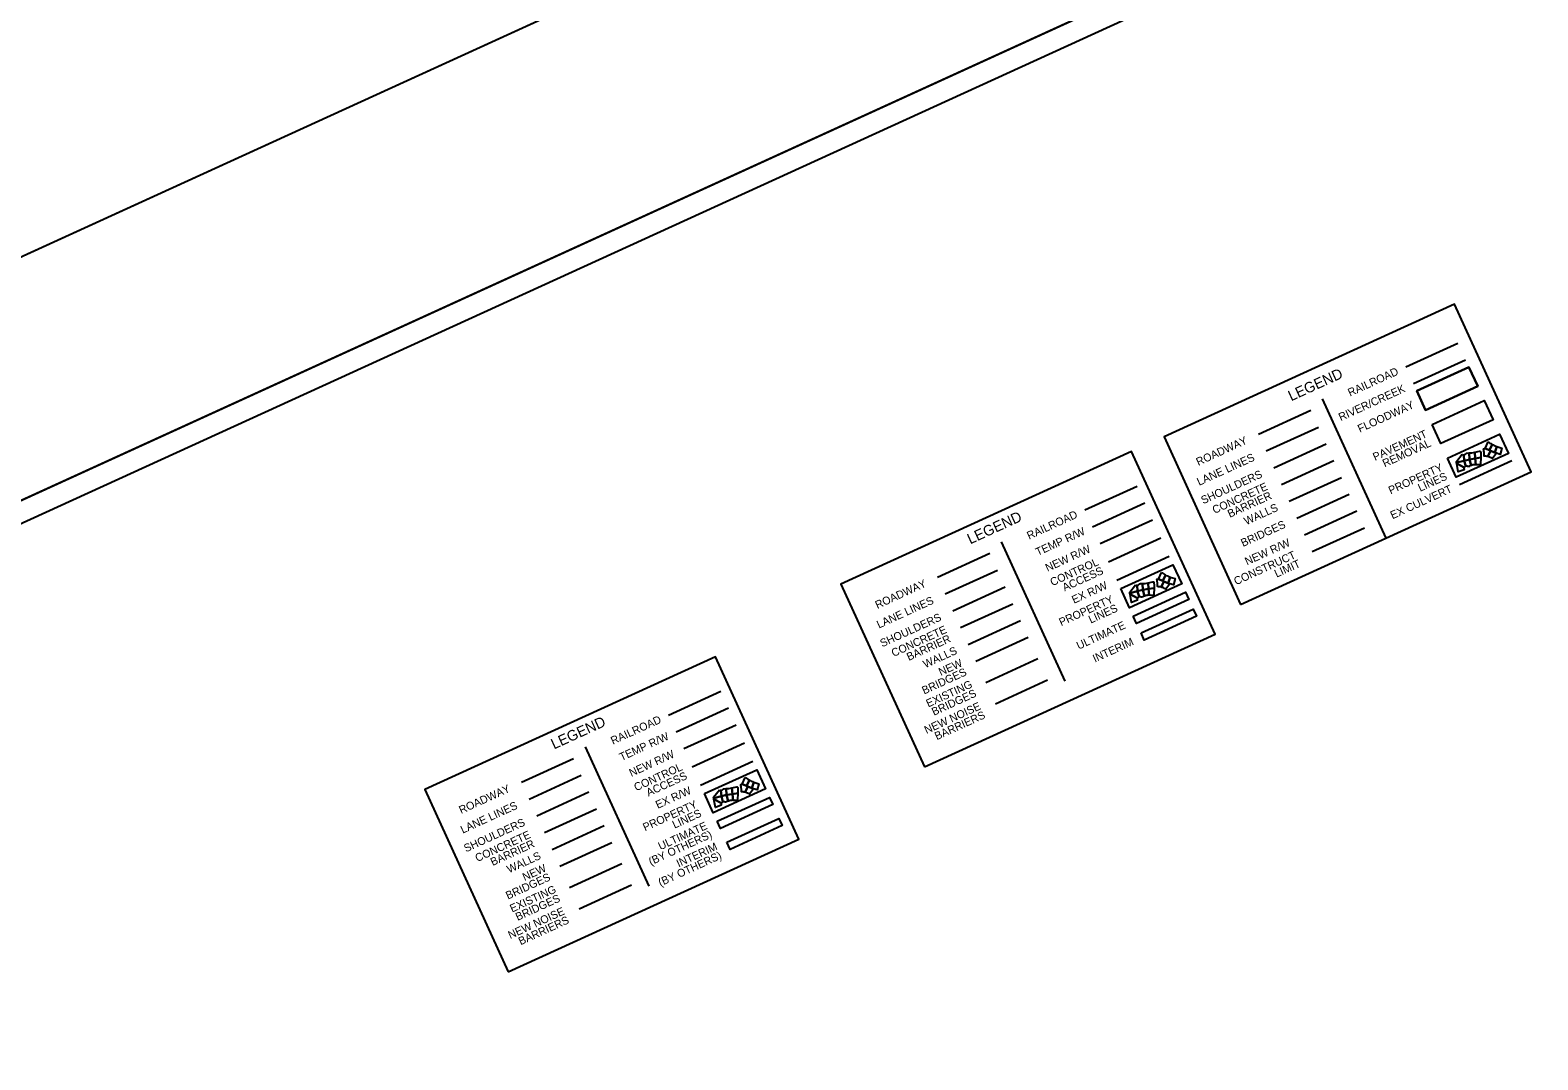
# Model space of a CAD drawing. Extents: x 1952253 to 1982336, y 791177 to 808695.
# Drawn here: x 1960851 to 1967995, y 791177 to 796057 of the extents above; entities that cross this region are included whole.
import ezdxf

# ---------------------------------------------------------------- set-up
doc = ezdxf.new("R2010")
doc.units = 0
for name, color, linetype in [('Default', 7, 'Continuous'), ('RD_SHT_Bndy', 7, 'Continuous'), ('RD_SHT_IplotShp', 7, 'Continuous'), ('RD_SHT_ShtClip', 7, 'Continuous'), ('RD_SHT_TX', 7, 'Continuous'), ('RD_Sketch1', 7, 'Continuous')]:
    doc.layers.add(name, color=color, linetype=linetype)

msp = doc.modelspace()

# ---------------------------------------------------------------- linework, layer by layer
at = {"layer": 'Default'}
for points in [[(1967759.2, 794105.8), (1967762.3, 794103.5), (1967767.2, 794100.2), (1967772.2, 794097.1), (1967777.2, 794094.1), (1967779.2, 794093), (1967765.5, 794065.6), (1967745, 794074.2)], [(1967779.2, 794093), (1967782.4, 794091.3), (1967787.7, 794088.7), (1967793, 794086.3), (1967798.4, 794084.1), (1967800.1, 794083.4), (1967790.8, 794055), (1967771.3, 794063.2), (1967765.5, 794065.6)], [(1967636.5, 794046.8), (1967638.1, 794045.9), (1967639.6, 794045.3), (1967641.1, 794044.9), (1967642.7, 794044.7), (1967644.3, 794044.7), (1967646.2, 794016.4), (1967610, 794007.3), (1967609.1, 794012.1)], [(1967646.2, 794016.4), (1967653.7, 793990), (1967652.2, 793989.5), (1967650.8, 793988.8), (1967649.5, 793987.9), (1967648.3, 793986.8), (1967647.3, 793985.7), (1967646.2, 793984.1), (1967610.9, 794002.4), (1967610, 794007.3)], [(1967652.9, 794049), (1967653.9, 794050), (1967655, 794050.8), (1967656.3, 794051.5), (1967657.6, 794052), (1967660, 794052.4), (1967668.8, 794052.9), (1967671, 794022.6), (1967646.2, 794016.4), (1967644.3, 794044.7), (1967646.2, 794045), (1967647.8, 794045.4), (1967649.2, 794046.1), (1967650.6, 794046.9), (1967651.8, 794047.9)], [(1967671, 794022.6), (1967678.4, 793993.3), (1967677.3, 793992.9), (1967674.1, 793991.4), (1967670.9, 793989.9), (1967670.4, 793989.6), (1967669.1, 793989.1), (1967667.7, 793988.8), (1967666.3, 793988.7), (1967664.9, 793988.7), (1967663.5, 793989), (1967662.2, 793989.5), (1967661.5, 793989.8), (1967660, 793990.2), (1967658.4, 793990.5), (1967656.8, 793990.5), (1967655.3, 793990.4), (1967653.7, 793990), (1967646.2, 794016.4)], [(1967696, 794056.5), (1967698.1, 794027.2), (1967671, 794022.6), (1967668.8, 794052.9), (1967681.8, 794053.5)], [(1967698.1, 794027.2), (1967701.4, 793997.3), (1967699.6, 793997.3), (1967698, 793997.3), (1967694.5, 793997.1), (1967691, 793996.6), (1967687.5, 793996), (1967684.1, 793995.1), (1967680.7, 793994.1), (1967678.4, 793993.3), (1967671, 794022.6)], [(1967724.4, 794031.6), (1967698.1, 794027.2), (1967696, 794056.5), (1967719.1, 794061.3), (1967720.1, 794061.4), (1967721, 794061.3), (1967721.8, 794060.9), (1967722.5, 794060.4), (1967723, 794059.7), (1967723.4, 794059), (1967723.6, 794058.1), (1967724, 794054.5), (1967724.4, 794048.8), (1967724.7, 794043.1), (1967724.7, 794037.4)], [(1967724.4, 794031.6), (1967722.9, 794000.1), (1967722.9, 793999.5), (1967722.6, 793998.7), (1967722.1, 793997.9), (1967721.5, 793997.3), (1967720.7, 793996.9), (1967719.9, 793996.6), (1967719.1, 793996.6), (1967701.4, 793997.3), (1967698.1, 794027.2)], [(1967745, 794074.2), (1967765.5, 794065.6), (1967771.3, 794063.2), (1967758.5, 794035.5), (1967757.4, 794035.8), (1967753.3, 794036.7), (1967749.1, 794037.5), (1967744.9, 794038), (1967741.2, 794038.4), (1967741.1, 794044.4), (1967740.9, 794050.3), (1967740.4, 794056.3), (1967739.7, 794062.3), (1967738.8, 794068.2), (1967738, 794072.8)], [(1967771.3, 794063.2), (1967790.8, 794055), (1967799.1, 794052.1), (1967779.8, 794026.7), (1967777.1, 794028.2), (1967773.4, 794030.1), (1967769.5, 794031.8), (1967765.5, 794033.3), (1967761.5, 794034.6), (1967758.5, 794035.5)], [(1967800.1, 794083.4), (1967803.9, 794082), (1967805.2, 794081.6), (1967824.1, 794076.2), (1967815.6, 794046.3), (1967799.1, 794052.1), (1967790.8, 794055)], [(1967646.2, 793984.1), (1967645.7, 793982.9), (1967645.1, 793981.4), (1967644.8, 793979.9), (1967644.7, 793978.3), (1967644.7, 793976.7), (1967645, 793975.2), (1967645.5, 793973.7), (1967617.8, 793963.3), (1967610.9, 794002.4)], [(1966176.6, 793412.8), (1966150.3, 793408.4), (1966148.1, 793437.7), (1966171.2, 793442.6), (1966172.3, 793442.7), (1966173.1, 793442.5), (1966173.9, 793442.2), (1966174.6, 793441.7), (1966175.1, 793441), (1966175.5, 793440.2), (1966175.7, 793439.4), (1966176.1, 793435.7), (1966176.6, 793430.1), (1966176.8, 793424.4), (1966176.9, 793418.6)], [(1966197.1, 793455.5), (1966217.6, 793446.9), (1966223.4, 793444.4), (1966210.6, 793416.7), (1966209.6, 793417), (1966205.4, 793418), (1966201.3, 793418.7), (1966197.1, 793419.3), (1966193.4, 793419.6), (1966193.3, 793425.6), (1966193, 793431.6), (1966192.5, 793437.6), (1966191.8, 793443.5), (1966191, 793449.4), (1966190.1, 793454.1)], [(1966211.3, 793487), (1966214.5, 793484.7), (1966219.3, 793481.4), (1966224.3, 793478.3), (1966229.4, 793475.4), (1966231.4, 793474.3), (1966217.6, 793446.9), (1966197.1, 793455.5)], [(1966223.4, 793444.4), (1966243, 793436.2), (1966251.3, 793433.3), (1966231.9, 793407.9), (1966229.3, 793409.4), (1966225.5, 793411.3), (1966221.6, 793413), (1966217.7, 793414.6), (1966213.6, 793415.9), (1966210.6, 793416.7)], [(1966231.4, 793474.3), (1966234.5, 793472.6), (1966239.8, 793470), (1966245.1, 793467.6), (1966250.6, 793465.3), (1966252.3, 793464.7), (1966243, 793436.2), (1966223.4, 793444.4), (1966217.6, 793446.9)], [(1966252.3, 793464.7), (1966256.1, 793463.3), (1966257.4, 793462.8), (1966276.2, 793457.4), (1966267.8, 793427.6), (1966251.3, 793433.3), (1966243, 793436.2)], [(1966088.7, 793428.1), (1966090.3, 793427.1), (1966091.7, 793426.6), (1966093.3, 793426.2), (1966094.8, 793426), (1966096.4, 793426), (1966098.3, 793397.6), (1966062.1, 793388.5), (1966061.3, 793393.4)], [(1966098.3, 793397.6), (1966105.8, 793371.3), (1966104.3, 793370.8), (1966102.9, 793370), (1966101.6, 793369.2), (1966100.4, 793368.1), (1966099.4, 793366.9), (1966098.4, 793365.3), (1966063, 793383.6), (1966062.1, 793388.5)], [(1966098.4, 793365.3), (1966097.8, 793364.2), (1966097.3, 793362.7), (1966097, 793361.2), (1966096.8, 793359.6), (1966096.9, 793358), (1966097.2, 793356.4), (1966097.6, 793354.9), (1966069.9, 793344.6), (1966063, 793383.6)], [(1966105.1, 793430.3), (1966106, 793431.3), (1966107.2, 793432.1), (1966108.4, 793432.8), (1966109.7, 793433.3), (1966112.1, 793433.7), (1966120.9, 793434.1), (1966123.2, 793403.9), (1966098.3, 793397.6), (1966096.4, 793426), (1966098.4, 793426.3), (1966099.9, 793426.7), (1966101.3, 793427.3), (1966102.7, 793428.2), (1966103.9, 793429.1)], [(1966123.2, 793403.9), (1966130.6, 793374.5), (1966129.5, 793374.1), (1966126.2, 793372.7), (1966123.1, 793371.1), (1966122.6, 793370.9), (1966121.2, 793370.4), (1966119.9, 793370), (1966118.5, 793369.9), (1966117, 793370), (1966115.7, 793370.3), (1966114.3, 793370.8), (1966113.6, 793371), (1966112.1, 793371.5), (1966110.6, 793371.7), (1966109, 793371.8), (1966107.4, 793371.7), (1966105.8, 793371.3), (1966098.3, 793397.6)], [(1966148.1, 793437.7), (1966150.3, 793408.4), (1966123.2, 793403.9), (1966120.9, 793434.1), (1966133.9, 793434.7)], [(1966150.3, 793408.4), (1966153.6, 793378.5), (1966151.7, 793378.6), (1966150.2, 793378.6), (1966146.6, 793378.3), (1966143.1, 793377.9), (1966139.6, 793377.2), (1966136.2, 793376.4), (1966132.8, 793375.3), (1966130.6, 793374.5), (1966123.2, 793403.9)], [(1966176.6, 793412.8), (1966175.1, 793381.4), (1966175, 793380.7), (1966174.7, 793379.9), (1966174.2, 793379.2), (1966173.6, 793378.6), (1966172.9, 793378.1), (1966172.1, 793377.9), (1966171.2, 793377.8), (1966153.6, 793378.5), (1966150.3, 793408.4)], [(1964239.3, 792515), (1964242.5, 792512.7), (1964247.3, 792509.4), (1964252.3, 792506.3), (1964257.4, 792503.4), (1964259.4, 792502.3), (1964245.6, 792474.9), (1964225.1, 792483.5)], [(1964116.7, 792456.1), (1964118.3, 792455.1), (1964119.8, 792454.6), (1964121.3, 792454.2), (1964122.9, 792454), (1964124.4, 792454), (1964126.3, 792425.6), (1964090.1, 792416.5), (1964089.3, 792421.4)], [(1964133.1, 792458.3), (1964134.1, 792459.3), (1964135.2, 792460.1), (1964136.4, 792460.8), (1964137.7, 792461.3), (1964140.1, 792461.7), (1964148.9, 792462.1), (1964151.2, 792431.9), (1964126.3, 792425.6), (1964124.4, 792454), (1964126.4, 792454.3), (1964127.9, 792454.7), (1964129.3, 792455.3), (1964130.7, 792456.1), (1964131.9, 792457.1)], [(1964176.1, 792465.7), (1964178.3, 792436.4), (1964151.2, 792431.9), (1964148.9, 792462.1), (1964161.9, 792462.7)], [(1964204.6, 792440.8), (1964178.3, 792436.4), (1964176.1, 792465.7), (1964199.2, 792470.6), (1964200.3, 792470.7), (1964201.1, 792470.5), (1964201.9, 792470.2), (1964202.6, 792469.6), (1964203.2, 792469), (1964203.5, 792468.2), (1964203.7, 792467.4), (1964204.1, 792463.7), (1964204.6, 792458), (1964204.8, 792452.3), (1964204.9, 792446.6)], [(1964225.1, 792483.5), (1964245.6, 792474.9), (1964251.4, 792472.4), (1964238.6, 792444.7), (1964237.6, 792445), (1964233.4, 792446), (1964229.3, 792446.7), (1964225.1, 792447.3), (1964221.4, 792447.6), (1964221.3, 792453.6), (1964221, 792459.6), (1964220.5, 792465.6), (1964219.8, 792471.5), (1964219, 792477.4), (1964218.1, 792482)], [(1964251.4, 792472.4), (1964271, 792464.2), (1964279.3, 792461.3), (1964259.9, 792435.9), (1964257.3, 792437.4), (1964253.5, 792439.3), (1964249.6, 792441), (1964245.7, 792442.5), (1964241.6, 792443.9), (1964238.6, 792444.7)], [(1964259.4, 792502.3), (1964262.5, 792500.6), (1964267.8, 792498), (1964273.1, 792495.6), (1964278.6, 792493.3), (1964280.3, 792492.7), (1964271, 792464.2), (1964251.4, 792472.4), (1964245.6, 792474.9)], [(1964280.3, 792492.7), (1964284.1, 792491.3), (1964285.4, 792490.8), (1964304.2, 792485.4), (1964295.8, 792455.6), (1964279.3, 792461.3), (1964271, 792464.2)], [(1964126.3, 792425.6), (1964133.8, 792399.3), (1964132.3, 792398.8), (1964130.9, 792398), (1964129.6, 792397.1), (1964128.4, 792396.1), (1964127.4, 792394.9), (1964126.4, 792393.3), (1964091, 792411.6), (1964090.1, 792416.5)], [(1964126.4, 792393.3), (1964125.8, 792392.2), (1964125.3, 792390.7), (1964125, 792389.1), (1964124.8, 792387.6), (1964124.9, 792386), (1964125.2, 792384.4), (1964125.6, 792382.9), (1964098, 792372.6), (1964091, 792411.6)], [(1964151.2, 792431.9), (1964158.6, 792402.5), (1964157.5, 792402.1), (1964154.2, 792400.7), (1964151.1, 792399.1), (1964150.6, 792398.9), (1964149.2, 792398.4), (1964147.9, 792398), (1964146.5, 792397.9), (1964145, 792398), (1964143.7, 792398.3), (1964142.3, 792398.8), (1964141.6, 792399), (1964140.1, 792399.5), (1964138.6, 792399.7), (1964137, 792399.8), (1964135.4, 792399.7), (1964133.8, 792399.3), (1964126.3, 792425.6)], [(1964178.3, 792436.4), (1964181.6, 792406.5), (1964179.7, 792406.6), (1964178.2, 792406.6), (1964174.6, 792406.3), (1964171.1, 792405.9), (1964167.6, 792405.2), (1964164.2, 792404.4), (1964160.8, 792403.3), (1964158.6, 792402.5), (1964151.2, 792431.9)], [(1964204.6, 792440.8), (1964203.1, 792409.4), (1964203, 792408.7), (1964202.7, 792407.9), (1964202.2, 792407.2), (1964201.6, 792406.6), (1964200.9, 792406.1), (1964200.1, 792405.9), (1964199.2, 792405.8), (1964181.6, 792406.5), (1964178.3, 792436.4)]]:
    msp.add_lwpolyline(points, close=True, dxfattribs=at)
at = {"layer": 'RD_SHT_Bndy'}
for p, q in [((1966973.1, 794310.3), (1967274.8, 793649.8)), ((1965452.3, 793632.2), (1965754.1, 792971.7)), ((1963480.3, 792660.2), (1963782.1, 791999.7))]:
    msp.add_line(p, q, dxfattribs=at)
for points in [[(1979125.3, 802195.5), (1955294.1, 791309), (1952385.5, 797676.1), (1976216.7, 808562.6)], [(1959270.9, 793125.7), (1973897.5, 799807.4), (1973461.2, 800762.4), (1958834.7, 794080.8)], [(1966586.5, 793335.4), (1967963.1, 793964.2), (1967600.3, 794758.5), (1966223.7, 794129.6)], [(1965088.5, 792565.1), (1966465.2, 793194), (1966069.8, 794059.5), (1964693.1, 793430.6)], [(1966018.4, 793410.2), (1966266, 793523.3), (1966307.5, 793432.4), (1966059.9, 793319.3)], [(1963116.5, 791593.1), (1964493.2, 792222), (1964097.8, 793087.5), (1962721.1, 792458.6)], [(1964046.4, 792438.2), (1964294, 792551.3), (1964335.5, 792460.4), (1964088, 792347.3)]]:
    msp.add_lwpolyline(points, close=True, dxfattribs=at)
at = {"layer": 'RD_SHT_IplotShp'}
msp.add_lwpolyline([(1979257.8, 802146.1), (1955244.7, 791176.5), (1952253, 797725.5), (1976266.1, 808695.1)], close=True, dxfattribs=at)
at = {"layer": 'RD_SHT_ShtClip'}
msp.add_lwpolyline([(1978689, 803150.6), (1954857.8, 792264.1), (1952385.5, 797676.1), (1976216.7, 808562.6)], close=True, dxfattribs=at)
msp.add_lwpolyline([(1978689, 803150.6), (1954857.8, 792264.1), (1952385.5, 797676.1), (1976216.7, 808562.6)], close=True, dxfattribs=at)
msp.add_lwpolyline([(1978689, 803150.6), (1954857.8, 792264.1), (1952385.5, 797676.1), (1976216.7, 808562.6)], close=True, dxfattribs=at)
msp.add_lwpolyline([(1978689, 803150.6), (1954857.8, 792264.1), (1952385.5, 797676.1), (1976216.7, 808562.6)], close=True, dxfattribs=at)
at = {"layer": 'RD_Sketch1'}
for p, q in [((1967368.9, 794461), (1967616.5, 794574.1)), ((1967405.2, 794381.5), (1967652.8, 794494.5)), ((1966671.5, 794142.4), (1966919, 794255.5)), ((1966707.8, 794062.9), (1966955.4, 794175.9)), ((1966744.2, 793983.3), (1966991.7, 794096.4)), ((1966780.5, 793903.7), (1967028.1, 794016.8)), ((1967623.4, 793903.9), (1967871, 794017)), ((1965848.2, 793782.9), (1966095.7, 793896)), ((1966816.9, 793824.1), (1967064.5, 793937.2)), ((1965884.5, 793703.3), (1966132.1, 793816.4)), ((1966853.2, 793744.5), (1967100.8, 793857.6)), ((1965920.9, 793623.7), (1966168.5, 793736.8)), ((1966889.6, 793664.9), (1967137.2, 793778)), ((1966926, 793585.3), (1967173.5, 793698.4)), ((1965960.3, 793537.4), (1966207.9, 793650.5)), ((1965150.7, 793464.3), (1965398.3, 793577.4)), ((1966000, 793450.7), (1966247.5, 793563.8)), ((1965187.1, 793384.7), (1965434.7, 793497.8)), ((1965223.5, 793305.1), (1965471, 793418.2)), ((1965259.8, 793225.5), (1965507.4, 793338.6)), ((1965296.2, 793145.9), (1965543.7, 793259)), ((1965332.5, 793066.4), (1965580.1, 793179.5)), ((1965378.6, 792965.5), (1965626.2, 793078.5)), ((1965424.7, 792864.5), (1965672.3, 792977.6)), ((1963876.2, 792810.9), (1964123.7, 792924)), ((1963912.5, 792731.3), (1964160.1, 792844.4)), ((1963948.9, 792651.7), (1964196.5, 792764.8)), ((1963988.3, 792565.4), (1964235.9, 792678.5)), ((1963178.7, 792492.3), (1963426.3, 792605.4)), ((1964028, 792478.7), (1964275.5, 792591.8)), ((1963215.1, 792412.7), (1963462.7, 792525.8)), ((1963251.5, 792333.1), (1963499, 792446.2)), ((1963287.8, 792253.5), (1963535.4, 792366.6)), ((1963324.2, 792173.9), (1963571.7, 792287)), ((1963360.5, 792094.4), (1963608.1, 792207.4)), ((1963406.6, 791993.4), (1963654.2, 792106.5)), ((1963452.7, 791892.5), (1963700.3, 792005.6))]:
    msp.add_line(p, q, dxfattribs=at)
for points in [[(1967420.8, 794347.3), (1967668.4, 794460.4), (1967709.9, 794369.5), (1967462.4, 794256.4)], [(1967493.5, 794188.2), (1967741.1, 794301.3), (1967782.7, 794210.3), (1967535.1, 794097.2)], [(1967566.3, 794029), (1967813.8, 794142.1), (1967855.4, 794051.1), (1967607.8, 793938)], [(1966078.2, 793279.4), (1966325.8, 793392.6), (1966341.4, 793358.4), (1966093.8, 793245.3)], [(1966114.6, 793199.9), (1966362.1, 793313), (1966377.7, 793278.8), (1966130.2, 793165.7)], [(1964106.2, 792307.4), (1964353.8, 792420.6), (1964369.4, 792386.4), (1964121.8, 792273.3)], [(1964151.7, 792207.8), (1964399.3, 792321), (1964414.9, 792286.8), (1964167.3, 792173.7)]]:
    msp.add_lwpolyline(points, close=True, dxfattribs=at)
msp.add_lwpolyline([(1967462.4, 794256.4), (1967709.9, 794369.5), (1967668.4, 794460.4), (1967420.8, 794347.3), (1967462.4, 794256.4)], dxfattribs=at)

# ---------------------------------------------------------------- texts
at = {"layer": 'RD_SHT_TX'}
for s, height, p in [('LEGEND', 50, (1966825.9, 794297.5)), ('RAILROAD', 37.5, (1967105.1, 794319.9)), ('RIVER/CREEK', 37.5, (1967061, 794203.6)), ('FLOODWAY', 37.5, (1967151.5, 794148.7)), ('PAVEMENT', 37.5, (1967223.4, 794015)), ('ROADWAY', 37.5, (1966386.1, 793991.5)), ('REMOVAL', 37.5, (1967269.3, 793984.4)), ('LANE LINES', 38, (1966389.9, 793896.8)), ('SHOULDERS', 37.5, (1966409.2, 793809.6)), ('PROPERTY ', 37.5, (1967297.4, 793856.4)), ('LINES', 37.5, (1967437.3, 793868.7)), ('CONCRETE', 37.5, (1966462.9, 793763.7)), ('EX CULVERT', 37.5, (1967306.2, 793738.4)), ('BARRIER', 37.5, (1966535.3, 793745.2)), ('WALLS', 37.5, (1966613.2, 793710.4)), ('LEGEND', 50, (1965305.2, 793619.4)), ('RAILROAD', 37.5, (1965584.4, 793641.8)), ('BRIDGES', 37.5, (1966598.1, 793607.3)), ('TEMP R/W', 37.5, (1965625.3, 793564.3)), ('NEW R/W ', 37.5, (1965671.8, 793489.3)), ('CONSTRUCT', 37.5, (1966565.2, 793425.7)), ('NEW R/W ', 37.5, (1966617.1, 793519.8)), ('CONTROL', 37.5, (1965694.6, 793421.2)), ('LIMIT', 37.5, (1966757.1, 793461.8)), ('ROADWAY', 37.5, (1964865.4, 793313.3)), ('ACCESS', 37.5, (1965752.7, 793396.1)), ('EX R/W ', 37.5, (1965797, 793337.8)), ('PROPERTY ', 37.5, (1965736.5, 793231.7)), ('LANE LINES', 37.5, (1964872.7, 793220.5)), ('LINES', 37.5, (1965876.4, 793244)), ('SHOULDERS', 37.5, (1964888.5, 793131.5)), ('CONCRETE', 37.5, (1964942.2, 793085.6)), ('ULTIMATE', 37.5, (1965819.4, 793120.4)), ('BARRIER', 37.5, (1965014.5, 793067.1)), ('INTERIM', 37.5, (1965896.3, 793059.4)), ('WALLS', 37.5, (1965092.5, 793032.3)), ('BRIDGES', 37.5, (1965087.1, 792907.9)), ('NEW', 37.5, (1965166.1, 792995.5)), ('EXISTING', 37.5, (1965106.7, 792846.4)), ('NEW NOISE', 37.5, (1965098.3, 792720.5)), ('BRIDGES', 37.5, (1965133.2, 792807)), ('LEGEND', 50, (1963333.2, 792647.4)), ('RAILROAD', 37.5, (1963612.4, 792669.8)), ('BARRIERS', 37.5, (1965147.3, 792691.4)), ('TEMP R/W', 37.5, (1963653.3, 792592.3)), ('NEW R/W ', 37.5, (1963699.8, 792517.3)), ('CONTROL', 37.5, (1963722.6, 792449.2)), ('ACCESS', 37.5, (1963780.7, 792424.1)), ('ROADWAY', 37.5, (1962893.4, 792341.3)), ('EX R/W ', 37.5, (1963825, 792365.8)), ('LANE LINES', 37.5, (1962900.7, 792248.5)), ('PROPERTY ', 37.5, (1963764.6, 792259.7)), ('SHOULDERS', 37.5, (1962916.5, 792159.5)), ('ULTIMATE', 37.5, (1963837.6, 792169.7)), ('LINES', 37.5, (1963904.4, 792272)), ('CONCRETE', 37.5, (1962970.2, 792113.6)), ('(BY OTHERS)', 37.5, (1963792.1, 792097.4)), ('BARRIER', 37.5, (1963042.5, 792095.1)), ('WALLS', 37.5, (1963120.5, 792060.3)), ('(BY OTHERS)', 37.5, (1963837.6, 791997.8)), ('INTERIM', 37.5, (1963923.7, 792088.7)), ('NEW', 37.5, (1963194.1, 792023.5)), ('BRIDGES', 37.5, (1963115.1, 791935.9)), ('EXISTING', 37.5, (1963134.7, 791874.4)), ('BRIDGES', 37.5, (1963161.2, 791835)), ('NEW NOISE', 37.5, (1963126.3, 791748.5)), ('BARRIERS', 37.5, (1963175.3, 791719.4))]:
    msp.add_text(s, height=height, rotation=24.55175, dxfattribs=at).set_placement(p)

doc.saveas('drawing.dxf')
